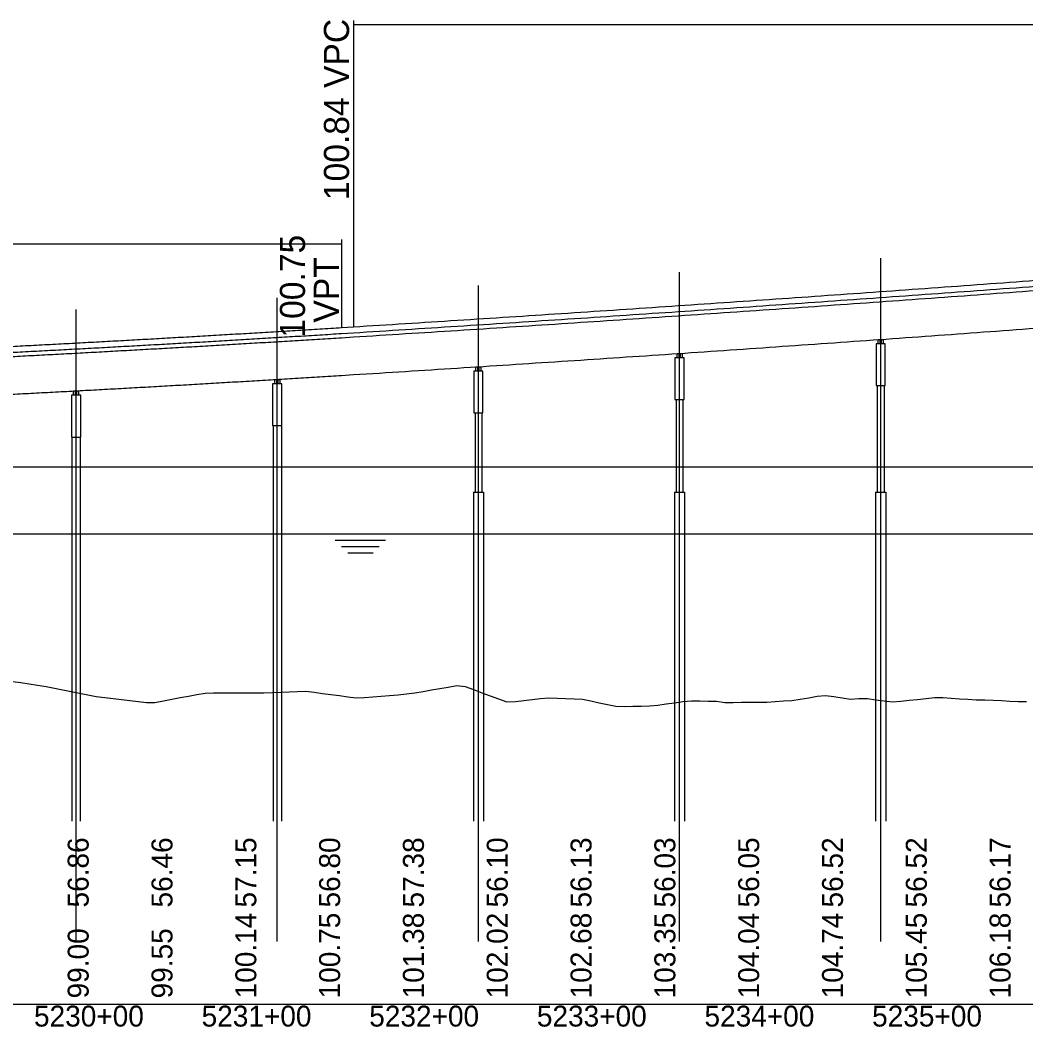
# Model space of a CAD drawing. Extents: x 2121671 to 2169879, y 557274 to 599957.
# Drawn here: x 2152526 to 2153126, y 579173 to 579774 of the extents above; entities that cross this region are included whole.
import ezdxf

# ---------------------------------------------------------------- set-up
doc = ezdxf.new("R2010")
doc.units = 0
for name, color, linetype in [('BR_CENTER LINES', 7, 'Continuous'), ('BR_CONCRETE', 7, 'Continuous'), ('BR_DETAILS', 7, 'Continuous'), ('BR_PRESTRESSED BEAM', 7, 'Continuous'), ('RD_DDB_Profile_Elev', 7, 'Continuous'), ('RD_DDB_Profile_EX', 7, 'Continuous'), ('RD_DDB_Profile_PR', 7, 'Continuous'), ('RD_DDB_StaTX', 7, 'Continuous'), ('RD_DDB_StripGrade', 7, 'Continuous'), ('RD_DDB_VCLbl', 7, 'Continuous'), ('RD_GPK_Profile_Cell', 7, 'Continuous')]:
    doc.layers.add(name, color=color, linetype=linetype)

msp = doc.modelspace()

# ---------------------------------------------------------------- linework, layer by layer
at = {"layer": 'BR_CENTER LINES'}
for p, q in [((2153039.43, 579224.3), (2153039.43, 579632.04)), ((2152919.43, 579224.3), (2152919.43, 579623.69)), ((2152799.43, 579224.3), (2152799.43, 579615.74)), ((2152679.43, 579224.3), (2152679.43, 579608.2)), ((2152559.43, 579224.3), (2152559.43, 579601.35))]:
    msp.add_line(p, q, dxfattribs=at)
at = {"layer": 'BR_CONCRETE'}
for p, q in [((2152717.84, 579587.02), (2152724.93, 579587.46)), ((2153037.43, 579555.89), (2153037.43, 579492.43)), ((2153041.43, 579555.89), (2153041.43, 579492.43)), ((2152917.43, 579547.54), (2152917.43, 579492.43)), ((2152921.43, 579547.54), (2152921.43, 579492.43)), ((2152797.43, 579539.6), (2152797.43, 579492.43)), ((2152801.43, 579539.6), (2152801.43, 579492.43)), ((2152676.93, 579532.07), (2152676.93, 579296.09)), ((2152681.93, 579532.07), (2152681.93, 579296.09)), ((2152556.93, 579525.23), (2152556.93, 579296.09)), ((2152561.93, 579525.23), (2152561.93, 579296.09)), ((2152796.43, 579492.43), (2152796.43, 579296.09)), ((2152796.43, 579492.43), (2152802.43, 579492.43)), ((2152802.43, 579492.43), (2152802.43, 579296.09)), ((2152916.43, 579492.43), (2152916.43, 579296.09)), ((2152916.43, 579492.43), (2152922.43, 579492.43)), ((2152922.43, 579492.43), (2152922.43, 579296.09)), ((2153036.43, 579492.43), (2153036.43, 579296.09)), ((2153036.43, 579492.43), (2153042.43, 579492.43)), ((2153042.43, 579492.43), (2153042.43, 579296.09))]:
    msp.add_line(p, q, dxfattribs=at)
for points in [[(2153036.68, 579555.89), (2153042.18, 579555.89), (2153042.18, 579580.89), (2153036.68, 579580.89)], [(2152916.68, 579547.54), (2152922.18, 579547.54), (2152922.18, 579572.54), (2152916.68, 579572.54)], [(2152796.68, 579539.6), (2152802.18, 579539.6), (2152802.18, 579564.6), (2152796.68, 579564.6)], [(2152676.68, 579532.07), (2152682.18, 579532.07), (2152682.18, 579557.07), (2152676.68, 579557.07)], [(2152556.68, 579525.23), (2152562.18, 579525.23), (2152562.18, 579550.23), (2152556.68, 579550.23)]]:
    msp.add_lwpolyline(points, close=True, dxfattribs=at)
for points in [[(2152724.93, 579587.46), (2152755.93, 579589.42), (2152786.93, 579591.39), (2152817.93, 579593.4), (2152848.93, 579595.43), (2152879.93, 579597.48), (2152910.93, 579599.57), (2152941.93, 579601.68), (2152972.93, 579603.82), (2153003.93, 579605.98), (2153034.93, 579608.17), (2153065.93, 579610.39), (2153096.93, 579612.64), (2153127.93, 579614.91), (2153158.93, 579617.21), (2153189.93, 579619.53), (2153220.93, 579621.88), (2153251.93, 579624.26), (2153282.93, 579626.67), (2153313.93, 579629.1), (2153344.93, 579631.56), (2153375.93, 579634.04), (2153406.93, 579636.55), (2153437.93, 579639.09), (2153468.93, 579641.66), (2153499.93, 579644.25), (2153530.93, 579646.87), (2153561.93, 579649.52), (2153592.93, 579652.19), (2153623.93, 579654.89), (2153654.93, 579657.61), (2153685.93, 579660.37), (2153716.93, 579663.15), (2153747.93, 579665.95), (2153778.93, 579668.79), (2153809.93, 579671.65), (2153840.93, 579674.53), (2153871.93, 579677.45), (2153902.93, 579680.39), (2153933.93, 579683.35), (2153964.93, 579686.35), (2153995.93, 579689.37), (2154026.93, 579692.42), (2154057.93, 579695.49), (2154088.93, 579698.59), (2154119.93, 579701.72), (2154150.93, 579704.87), (2154181.93, 579708.05), (2154212.93, 579711.26), (2154243.93, 579714.5), (2154274.93, 579717.76)], [(2152067.84, 579557.94), (2152080.84, 579558.29), (2152093.84, 579558.66), (2152106.84, 579559.03), (2152119.84, 579559.42), (2152132.84, 579559.81), (2152145.84, 579560.21), (2152158.84, 579560.62), (2152171.84, 579561.04), (2152184.84, 579561.47), (2152197.84, 579561.91), (2152210.84, 579562.36), (2152223.84, 579562.82), (2152236.84, 579563.28), (2152249.84, 579563.76), (2152262.84, 579564.24), (2152275.84, 579564.74), (2152288.84, 579565.24), (2152301.84, 579565.75), (2152314.84, 579566.27), (2152327.84, 579566.8), (2152340.84, 579567.34), (2152353.84, 579567.89), (2152366.84, 579568.45), (2152379.84, 579569.02), (2152392.84, 579569.6), (2152405.84, 579570.18), (2152418.84, 579570.78), (2152431.84, 579571.38), (2152444.84, 579572), (2152457.84, 579572.62), (2152470.84, 579573.25), (2152483.84, 579573.89), (2152496.84, 579574.55), (2152509.84, 579575.21), (2152522.84, 579575.87), (2152535.84, 579576.55), (2152548.84, 579577.24), (2152561.84, 579577.94), (2152574.84, 579578.64), (2152587.84, 579579.36), (2152600.84, 579580.08), (2152613.84, 579580.82), (2152626.84, 579581.56), (2152639.84, 579582.31), (2152652.84, 579583.08), (2152665.84, 579583.85), (2152678.84, 579584.63), (2152691.84, 579585.42), (2152704.84, 579586.21), (2152717.84, 579587.02)]]:
    msp.add_spline(points, degree=3, dxfattribs=at)
at = {"layer": 'BR_DETAILS'}
for points in [[(2153037.93, 579583.39), (2153038.93, 579583.39), (2153038.93, 579580.89), (2153037.93, 579580.89)], [(2153039.93, 579583.39), (2153040.93, 579583.39), (2153040.93, 579580.89), (2153039.93, 579580.89)], [(2152917.93, 579575.04), (2152918.93, 579575.04), (2152918.93, 579572.54), (2152917.93, 579572.54)], [(2152919.93, 579575.04), (2152920.93, 579575.04), (2152920.93, 579572.54), (2152919.93, 579572.54)], [(2152797.93, 579567.1), (2152798.93, 579567.1), (2152798.93, 579564.6), (2152797.93, 579564.6)], [(2152799.93, 579567.1), (2152800.93, 579567.1), (2152800.93, 579564.6), (2152799.93, 579564.6)], [(2152677.93, 579559.57), (2152678.93, 579559.57), (2152678.93, 579557.07), (2152677.93, 579557.07)], [(2152679.93, 579559.57), (2152680.93, 579559.57), (2152680.93, 579557.07), (2152679.93, 579557.07)], [(2152557.93, 579552.73), (2152558.93, 579552.73), (2152558.93, 579550.23), (2152557.93, 579550.23)], [(2152559.93, 579552.73), (2152560.93, 579552.73), (2152560.93, 579550.23), (2152559.93, 579550.23)]]:
    msp.add_lwpolyline(points, close=True, dxfattribs=at)
at = {"layer": 'BR_PRESTRESSED BEAM'}
for p, q in [((2152717.84, 579584.52), (2152724.93, 579584.96)), ((2152717.84, 579562.02), (2152724.93, 579562.46))]:
    msp.add_line(p, q, dxfattribs=at)
for points in [[(2152724.93, 579584.96), (2152755.93, 579586.92), (2152786.93, 579588.89), (2152817.93, 579590.9), (2152848.93, 579592.93), (2152879.93, 579594.98), (2152910.93, 579597.07), (2152941.93, 579599.18), (2152972.93, 579601.32), (2153003.93, 579603.48), (2153034.93, 579605.67), (2153065.93, 579607.89), (2153096.93, 579610.14), (2153127.93, 579612.41), (2153158.93, 579614.71), (2153189.93, 579617.03), (2153220.93, 579619.38), (2153251.93, 579621.76), (2153282.93, 579624.17), (2153313.93, 579626.6), (2153344.93, 579629.06), (2153375.93, 579631.54), (2153406.93, 579634.05), (2153437.93, 579636.59), (2153468.93, 579639.16), (2153499.93, 579641.75), (2153530.93, 579644.37), (2153561.93, 579647.02), (2153592.93, 579649.69), (2153623.93, 579652.39), (2153654.93, 579655.11), (2153685.93, 579657.87), (2153716.93, 579660.65), (2153747.93, 579663.45), (2153778.93, 579666.29), (2153809.93, 579669.15), (2153840.93, 579672.03), (2153871.93, 579674.95), (2153902.93, 579677.89), (2153933.93, 579680.85), (2153964.93, 579683.85), (2153995.93, 579686.87), (2154026.93, 579689.92), (2154057.93, 579692.99), (2154088.93, 579696.09), (2154119.93, 579699.22), (2154150.93, 579702.37), (2154181.93, 579705.55), (2154212.93, 579708.76), (2154243.93, 579712), (2154274.93, 579715.26)], [(2152724.93, 579562.46), (2152755.93, 579564.42), (2152786.93, 579566.39), (2152817.93, 579568.4), (2152848.93, 579570.43), (2152879.93, 579572.48), (2152910.93, 579574.57), (2152941.93, 579576.68), (2152972.93, 579578.82), (2153003.93, 579580.98), (2153034.93, 579583.17), (2153065.93, 579585.39), (2153096.93, 579587.64), (2153127.93, 579589.91), (2153158.93, 579592.21), (2153189.93, 579594.53), (2153220.93, 579596.88), (2153251.93, 579599.26), (2153282.93, 579601.67), (2153313.93, 579604.1), (2153344.93, 579606.56), (2153375.93, 579609.04), (2153406.93, 579611.55), (2153437.93, 579614.09), (2153468.93, 579616.66), (2153499.93, 579619.25), (2153530.93, 579621.87), (2153561.93, 579624.52), (2153592.93, 579627.19), (2153623.93, 579629.89), (2153654.93, 579632.61), (2153685.93, 579635.37), (2153716.93, 579638.15), (2153747.93, 579640.95), (2153778.93, 579643.79), (2153809.93, 579646.65), (2153840.93, 579649.53), (2153871.93, 579652.45), (2153902.93, 579655.39), (2153933.93, 579658.35), (2153964.93, 579661.35), (2153995.93, 579664.37), (2154026.93, 579667.42), (2154057.93, 579670.49), (2154088.93, 579673.59), (2154119.93, 579676.72), (2154150.93, 579679.87), (2154181.93, 579683.05), (2154212.93, 579686.26), (2154243.93, 579689.5), (2154274.93, 579692.76)], [(2152067.84, 579555.44), (2152080.84, 579555.79), (2152093.84, 579556.16), (2152106.84, 579556.53), (2152119.84, 579556.92), (2152132.84, 579557.31), (2152145.84, 579557.71), (2152158.84, 579558.12), (2152171.84, 579558.54), (2152184.84, 579558.97), (2152197.84, 579559.41), (2152210.84, 579559.86), (2152223.84, 579560.32), (2152236.84, 579560.78), (2152249.84, 579561.26), (2152262.84, 579561.74), (2152275.84, 579562.24), (2152288.84, 579562.74), (2152301.84, 579563.25), (2152314.84, 579563.77), (2152327.84, 579564.3), (2152340.84, 579564.84), (2152353.84, 579565.39), (2152366.84, 579565.95), (2152379.84, 579566.52), (2152392.84, 579567.1), (2152405.84, 579567.68), (2152418.84, 579568.28), (2152431.84, 579568.88), (2152444.84, 579569.5), (2152457.84, 579570.12), (2152470.84, 579570.75), (2152483.84, 579571.39), (2152496.84, 579572.05), (2152509.84, 579572.71), (2152522.84, 579573.37), (2152535.84, 579574.05), (2152548.84, 579574.74), (2152561.84, 579575.44), (2152574.84, 579576.14), (2152587.84, 579576.86), (2152600.84, 579577.58), (2152613.84, 579578.32), (2152626.84, 579579.06), (2152639.84, 579579.81), (2152652.84, 579580.58), (2152665.84, 579581.35), (2152678.84, 579582.13), (2152691.84, 579582.92), (2152704.84, 579583.71), (2152717.84, 579584.52)], [(2152067.84, 579532.94), (2152080.84, 579533.29), (2152093.84, 579533.66), (2152106.84, 579534.03), (2152119.84, 579534.42), (2152132.84, 579534.81), (2152145.84, 579535.21), (2152158.84, 579535.62), (2152171.84, 579536.04), (2152184.84, 579536.47), (2152197.84, 579536.91), (2152210.84, 579537.36), (2152223.84, 579537.82), (2152236.84, 579538.28), (2152249.84, 579538.76), (2152262.84, 579539.24), (2152275.84, 579539.74), (2152288.84, 579540.24), (2152301.84, 579540.75), (2152314.84, 579541.27), (2152327.84, 579541.8), (2152340.84, 579542.34), (2152353.84, 579542.89), (2152366.84, 579543.45), (2152379.84, 579544.02), (2152392.84, 579544.6), (2152405.84, 579545.18), (2152418.84, 579545.78), (2152431.84, 579546.38), (2152444.84, 579547), (2152457.84, 579547.62), (2152470.84, 579548.25), (2152483.84, 579548.89), (2152496.84, 579549.55), (2152509.84, 579550.21), (2152522.84, 579550.87), (2152535.84, 579551.55), (2152548.84, 579552.24), (2152561.84, 579552.94), (2152574.84, 579553.64), (2152587.84, 579554.36), (2152600.84, 579555.08), (2152613.84, 579555.82), (2152626.84, 579556.56), (2152639.84, 579557.31), (2152652.84, 579558.08), (2152665.84, 579558.85), (2152678.84, 579559.63), (2152691.84, 579560.42), (2152704.84, 579561.21), (2152717.84, 579562.02)]]:
    msp.add_spline(points, degree=3, dxfattribs=at)
at = {"layer": 'RD_DDB_Profile_Elev'}
for p, q in [((2151922.43, 579507.43), (2155499.43, 579507.43)), ((2151953.51, 579467.43), (2156316.65, 579467.43)), ((2152714.09, 579463.68), (2152744.09, 579463.68)), ((2152717.84, 579459.93), (2152740.34, 579459.93)), ((2152721.59, 579456.18), (2152736.59, 579456.18))]:
    msp.add_line(p, q, dxfattribs=at)
at = {"layer": 'RD_DDB_Profile_EX'}
for points in [[(2152521.48, 579379.48), (2152526.48, 579378.7), (2152531.48, 579377.91), (2152536.48, 579377.13), (2152541.48, 579376.34), (2152546.48, 579375.4), (2152551.48, 579374.4), (2152556.48, 579373.41), (2152561.48, 579372.42), (2152566.48, 579371.43), (2152571.48, 579370.44), (2152576.48, 579369.76), (2152581.48, 579369.16), (2152586.48, 579368.56), (2152591.48, 579367.97), (2152596.48, 579367.37), (2152601.48, 579366.77), (2152606.48, 579366.92), (2152611.48, 579367.88), (2152616.48, 579368.83), (2152621.48, 579369.78), (2152626.48, 579370.74), (2152631.48, 579371.69), (2152636.48, 579372.5), (2152641.48, 579372.54), (2152646.48, 579372.57), (2152651.48, 579372.6), (2152656.48, 579372.63), (2152661.48, 579372.66), (2152666.48, 579372.56), (2152671.48, 579372.65), (2152676.48, 579372.83), (2152681.48, 579373), (2152686.48, 579373.18), (2152691.48, 579373.35), (2152696.48, 579373.53), (2152701.48, 579372.98), (2152706.48, 579372.32), (2152711.48, 579371.66), (2152716.48, 579371), (2152721.48, 579370.34)], [(2152721.48, 579370.34), (2152726.48, 579369.68), (2152731.48, 579369.8), (2152736.48, 579370.24), (2152741.48, 579370.67), (2152746.48, 579371.11), (2152751.48, 579371.54), (2152756.48, 579371.98), (2152761.48, 579372.59), (2152766.48, 579373.46), (2152771.48, 579374.33), (2152776.48, 579375.19), (2152781.48, 579376.06), (2152786.48, 579376.93), (2152791.48, 579376.38), (2152796.48, 579374.55), (2152801.48, 579372.72), (2152806.48, 579370.89), (2152811.48, 579369.06), (2152816.48, 579367.23), (2152821.48, 579367.5), (2152826.48, 579368.08), (2152831.48, 579368.65), (2152836.48, 579369.23), (2152841.48, 579369.72), (2152846.48, 579369.48), (2152851.48, 579369.25), (2152856.48, 579369.02), (2152861.48, 579368.79), (2152866.48, 579367.79), (2152871.48, 579366.73), (2152876.48, 579365.67), (2152881.48, 579364.61), (2152886.48, 579364.54), (2152891.48, 579364.63), (2152896.48, 579364.73), (2152901.48, 579364.82), (2152906.48, 579365.3), (2152911.48, 579366.03), (2152916.48, 579366.76), (2152921.48, 579367.5), (2152926.48, 579367.88), (2152931.48, 579367.8), (2152936.48, 579367.72), (2152941.48, 579367.65), (2152946.48, 579366.91), (2152951.48, 579366.96), (2152956.48, 579367.02), (2152961.48, 579367.07), (2152966.48, 579367.06), (2152971.48, 579367.08), (2152976.48, 579367.44), (2152981.48, 579367.8), (2152986.48, 579368.16), (2152991.48, 579368.87), (2152996.48, 579369.75), (2153001.48, 579370.63), (2153006.48, 579371.07), (2153011.48, 579370.35), (2153016.48, 579369.62), (2153021.48, 579368.9), (2153026.48, 579369.28), (2153031.48, 579369.19), (2153036.48, 579368.53), (2153041.48, 579367.87), (2153046.48, 579367.21), (2153051.48, 579367.66), (2153056.48, 579368.2), (2153061.48, 579368.74), (2153066.48, 579369.29), (2153071.48, 579369.76), (2153076.48, 579369.82), (2153081.48, 579369.48), (2153086.48, 579369.14), (2153091.48, 579368.8), (2153096.48, 579368.46), (2153101.48, 579368.46), (2153106.48, 579368.21), (2153111.48, 579367.97), (2153116.48, 579367.73), (2153121.48, 579367.48), (2153126.48, 579367.37)]]:
    msp.add_lwpolyline(points, dxfattribs=at)
at = {"layer": 'RD_DDB_Profile_PR'}
msp.add_line((2152717.84, 579590.56), (2152724.93, 579591.01), dxfattribs=at)
for points in [[(2152724.93, 579591.01), (2152755.93, 579592.96), (2152786.93, 579594.93), (2152817.93, 579596.94), (2152848.93, 579598.97), (2152879.93, 579601.03), (2152910.93, 579603.11), (2152941.93, 579605.22), (2152972.93, 579607.36), (2153003.93, 579609.52), (2153034.93, 579611.71), (2153065.93, 579613.93), (2153096.93, 579616.18), (2153127.93, 579618.45), (2153158.93, 579620.75), (2153189.93, 579623.07), (2153220.93, 579625.42), (2153251.93, 579627.8), (2153282.93, 579630.21), (2153313.93, 579632.64), (2153344.93, 579635.1), (2153375.93, 579637.58), (2153406.93, 579640.1), (2153437.93, 579642.63), (2153468.93, 579645.2), (2153499.93, 579647.79), (2153530.93, 579650.41), (2153561.93, 579653.06), (2153592.93, 579655.73), (2153623.93, 579658.43), (2153654.93, 579661.16), (2153685.93, 579663.91), (2153716.93, 579666.69), (2153747.93, 579669.5), (2153778.93, 579672.33), (2153809.93, 579675.19), (2153840.93, 579678.08), (2153871.93, 579680.99), (2153902.93, 579683.93), (2153933.93, 579686.9), (2153964.93, 579689.89), (2153995.93, 579692.91), (2154026.93, 579695.96), (2154057.93, 579699.03), (2154088.93, 579702.13), (2154119.93, 579705.26), (2154150.93, 579708.41), (2154181.93, 579711.59), (2154212.93, 579714.8), (2154243.93, 579718.04), (2154274.93, 579721.3)], [(2152067.84, 579561.48), (2152080.84, 579561.84), (2152093.84, 579562.2), (2152106.84, 579562.57), (2152119.84, 579562.96), (2152132.84, 579563.35), (2152145.84, 579563.75), (2152158.84, 579564.16), (2152171.84, 579564.58), (2152184.84, 579565.01), (2152197.84, 579565.45), (2152210.84, 579565.9), (2152223.84, 579566.36), (2152236.84, 579566.82), (2152249.84, 579567.3), (2152262.84, 579567.78), (2152275.84, 579568.28), (2152288.84, 579568.78), (2152301.84, 579569.29), (2152314.84, 579569.81), (2152327.84, 579570.35), (2152340.84, 579570.89), (2152353.84, 579571.44), (2152366.84, 579571.99), (2152379.84, 579572.56), (2152392.84, 579573.14), (2152405.84, 579573.72), (2152418.84, 579574.32), (2152431.84, 579574.93), (2152444.84, 579575.54), (2152457.84, 579576.16), (2152470.84, 579576.79), (2152483.84, 579577.44), (2152496.84, 579578.09), (2152509.84, 579578.75), (2152522.84, 579579.42), (2152535.84, 579580.1), (2152548.84, 579580.78), (2152561.84, 579581.48), (2152574.84, 579582.19), (2152587.84, 579582.9), (2152600.84, 579583.63), (2152613.84, 579584.36), (2152626.84, 579585.1), (2152639.84, 579585.86), (2152652.84, 579586.62), (2152665.84, 579587.39), (2152678.84, 579588.17), (2152691.84, 579588.96), (2152704.84, 579589.76), (2152717.84, 579590.56)]]:
    msp.add_spline(points, degree=3, dxfattribs=at)
at = {"layer": 'RD_DDB_VCLbl'}
for p, q in [((2152724.93, 579773.8), (2152724.93, 579591.01)), ((2152724.93, 579771.3), (2154274.93, 579771.3)), ((2152067.84, 579640.56), (2152717.84, 579640.56)), ((2152717.84, 579643.06), (2152717.84, 579590.56))]:
    msp.add_line(p, q, dxfattribs=at)
at = {"layer": 'RD_GPK_Profile_Cell'}
msp.add_line((2151067.93, 579186.83), (2157367.93, 579186.83), dxfattribs=at)

# ---------------------------------------------------------------- texts
at = {"layer": 'RD_DDB_StaTX'}
for s, p in [('5230+00', (2152534.32, 579173.53)), ('5231+00', (2152634.32, 579173.53)), ('5232+00', (2152734.32, 579173.53)), ('5233+00', (2152834.32, 579173.53)), ('5234+00', (2152934.32, 579173.53)), ('5235+00', (2153034.32, 579173.53))]:
    msp.add_text(s, height=12.5, dxfattribs=at).set_placement(p)
at = {"layer": 'RD_DDB_StripGrade'}
for s, height, p in [('100.84 VPC', 15, (2152722.28, 579666.56)), ('100.75 ', 15, (2152696.01, 579584.56)), ('VPT', 15, (2152716.21, 579593.51)), ('56.86', 12.5, (2152566.93, 579244.56)), ('56.46', 12.5, (2152616.93, 579244.56)), ('57.15', 12.5, (2152666.93, 579244.56)), ('56.80', 12.5, (2152716.93, 579244.56)), ('57.38', 12.5, (2152766.93, 579244.56)), ('56.10', 12.5, (2152816.93, 579244.56)), ('56.13', 12.5, (2152866.93, 579244.56)), ('56.03', 12.5, (2152916.93, 579244.56)), ('56.05', 12.5, (2152966.93, 579244.56)), ('56.52', 12.5, (2153016.93, 579244.56)), ('56.52', 12.5, (2153066.93, 579244.56)), ('56.17', 12.5, (2153116.93, 579244.56)), ('100.14', 12.5, (2152666.93, 579190.33)), ('100.75', 12.5, (2152716.93, 579190.33)), ('101.38', 12.5, (2152766.93, 579190.33)), ('102.02', 12.5, (2152816.93, 579190.33)), ('102.68', 12.5, (2152866.93, 579190.33)), ('103.35', 12.5, (2152916.93, 579190.33)), ('104.04', 12.5, (2152966.93, 579190.33)), ('104.74', 12.5, (2153016.93, 579190.33)), ('105.45', 12.5, (2153066.93, 579190.33)), ('106.18', 12.5, (2153116.93, 579190.33)), ('99.00', 12.5, (2152566.93, 579190.33)), ('99.55', 12.5, (2152616.93, 579190.33))]:
    msp.add_text(s, height=height, rotation=90, dxfattribs=at).set_placement(p)

doc.saveas('drawing.dxf')
